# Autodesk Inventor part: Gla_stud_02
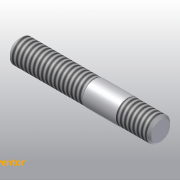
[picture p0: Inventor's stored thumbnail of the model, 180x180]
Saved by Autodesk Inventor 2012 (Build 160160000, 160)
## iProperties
Shininess: 64.0
Length Units: 11272
Angle Units: 11279
Time Units: 11290
Mass Units: 11286
Length Display Precision: 3
Angle Display Precision: 2
Compacted: True
Company: Autodesk
Created: 2002-07
Part Number: Gla_stud_02
Document SubType Name: Modeling
Designer: Lieven Grauls
Stock Number: Gla_stud_02
Project: Valve Techcamp 2008
Density: 1 g/cm^3
Mass: 2.36865 g
Surface Area: 12.7318 cm^2
Volume: 2.36865 cm^3
Material: Default
Density: 0.0
Volumn: 0.0
Area: 0.0
PropertySet Name: Model Information
Control State: 0
Master: False
Checked Out: False
Author: Lieven Grauls
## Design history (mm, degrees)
sketch "Sketch1"
  geometry: L1 (0, 0)-(0, 3.969); L2 (0, 3.969)-(25.4, 3.969); L3 (25.4, 3.969)-(25.4, 4.064); L4 (25.4, 4.064)-(36.5, 4.064); L5 (36.5, 4.064)-(36.5, 3.969); L6 (36.5, 3.969)-(47.625, 3.969); L7 (47.625, 3.969)-(47.625, 0); L8 (47.625, 0)-(0, 0)
  constraints: 16 end point, 5 parallel, 2 collinear, 1 perpendicular, 1 vertical
  dimensions: "d0" = 7.9375 diameter of L2 L8; "d1" = 8.128 diameter of L4 L8; "d2" = 25.4 distance of L1.end L2.end; "d3" = 11.1252 distance of L5.end L6.end; "d4" = 47.625 distance between parallel lines of L7 L1
revolve "Revolution1" sketch "Sketch1" stored, may be unused: angle "d5" = 90 deg
thread "Thread1" dims "d6" = 25.4, "d7" = 0
thread "Thread2" dims "d8" = 25.4, "d9" = 0
chamfer "Chamfer1" distance "d10" = 0.79375; stored, may be unused: second distance "d11" = 0.79375, angle "d12" = 45 deg
node "Volumenkörper1"
node "Volumenkörpern"
node "Oberflächenkörpern"
